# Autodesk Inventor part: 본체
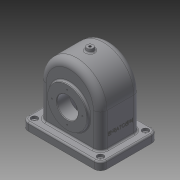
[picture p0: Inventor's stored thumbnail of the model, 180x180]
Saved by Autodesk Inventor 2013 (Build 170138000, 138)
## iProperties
Created: 2016-10
Part Number: 본체
Material: Generic
Document SubType Name: Modeling
Designer: Administrator
Density: 1 g/cm^3
Author: Administrator
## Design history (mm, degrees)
sketch "스케치1"
  geometry: L1 (-58, 65)-(58, 65); L2 (58, 65)-(58, 0); L3 (58, 0)-(-58, 0); L4 (-58, 0)-(-58, 65); L5 (-58, 65)-(-58, 80); L6 (58, 65)-(58, 80); A1 r 58 centre (0, 80) between (58, 80) and (-58, 80); 2 further points
  constraints: 12 end point, 3 parallel, 2 point on circle, 1 centre point, 1 coincident, 1 collinear, 1 horizontal, 1 midpoint, 1 perpendicular, 1 vertical alignment
  dimensions: "d0" = 116 distance of L2.end L3.end; "d2" = 65 distance of L1.end L2.end; "d4" = 80 distance of point (0, 0) A1.centre; "d5" = 58 radius of A1
extrude "돌출1" new body sketch "스케치1" stored distance "d6" = 77; taper "d7" = 0 deg
sketch "스케치2"
  geometry: L1 (58, 80)-(58, 0) reference; L2 (58, 0)-(-58, 0) reference; L3 (-58, 0)-(-58, 80) reference; L4 (52, 80)-(52, -10); L5 (-52, -10)-(-52, 80); L6 (-52, -10)-(52, -10); A1 r 58 centre (0, 80) between (58, 80) and (-58, 80) reference; A2 r 52 centre (0, 80) between (52, 80) and (-52, 80); 1 further point
  constraints: 6 end point, 2 point on circle, 1 centre point, 1 parallel, 1 perpendicular, 1 other
  dimensions: "d8" = 6 distance between parallel lines of L3 L5; "d9" = 52 radius of A2; "d10" = 10 distance between parallel lines of L6 L2
extrude "돌출2" cut sketch "스케치2" stored distance "d11" = 67; taper "d12" = 0 deg
fillet "모깎기1" dims "d13" = 8
fillet "모깎기2" dims "d14" = 13
sketch "스케치5"
  geometry: L1 (132, -25.5)-(132, 25.5) reference; L2 (124, 33.5)-(0, 33.5) reference; L3 (0, 33.5)-(0, 38.5) reference; L4 (0, 38.5)-(125, 38.5) reference; L5 (138, 25.5)-(138, -25.5) reference; L6 (125, -38.5)-(0, -38.5) reference; L7 (0, -38.5)-(0, -33.5) reference; L8 (0, -33.5)-(124, -33.5) reference; L9 (104.747, 33.5)-(93, 19.5); L10 (93, 19.5)-(65, 19.5); L11 (65, 43.5)-(102.5, 43.5); L12 (102.5, 43.5)-(102.5, 38.5); L13 (65, 19.5)-(65, 33.5); L14 (65, 38.5)-(65, 43.5); A1 r 8 centre (124, -25.5) between (124, -33.5) and (132, -25.5) reference; A2 r 8 centre (124, 25.5) between (132, 25.5) and (124, 33.5) reference; A3 r 13 centre (125, 25.5) between (138, 25.5) and (125, 38.5) reference; A4 r 13 centre (125, -25.5) between (125, -38.5) and (138, -25.5) reference; 1 further point
  constraints: 12 end point, 5 perpendicular, 4 point on line, 1 collinear, 1 parallel
  dimensions: "d15" = 65 distance from line of point (0, 0) L13; "d16" = 5 distance of L11.end L12.end; "d18" = 50 deg angle of L10 L9; "d19" = 56 diameter of L9.end L13; "d20" = 75 diameter of L12 L14; "d21" = 14 distance between parallel lines of L2 L10
revolve "회전1" sketch "스케치5" stored, may be unused: angle "d22" = 90 deg
sketch "스케치6"
  geometry: L1 (132, -25.5)-(132, 25.5) reference; L2 (124, 33.5)-(104.747, 33.5) reference; L3 (104.747, 33.5)-(93, 19.5) reference; L4 (93, 19.5)-(37, 19.5) reference; L5 (37, 19.5)-(25.253, 33.5) reference; L6 (25.253, 33.5)-(0, 33.5) reference; L7 (0, 33.5)-(0, 38.5) reference; L8 (0, 38.5)-(27.5, 38.5) reference; L9 (27.5, 38.5)-(27.5, 43.5) reference; L10 (27.5, 43.5)-(102.5, 43.5) reference; L11 (102.5, 43.5)-(102.5, 38.5) reference; L12 (102.5, 38.5)-(125, 38.5) reference; L13 (138, 25.5)-(138, -25.5) reference; L14 (125, -38.5)-(0, -38.5) reference; L15 (0, -38.5)-(0, -33.5) reference; L16 (0, -33.5)-(124, -33.5) reference; L17 (96, -38.5)-(65, -38.5); L18 (65, -38.5)-(65, -48.5); L19 (65, -48.5)-(96, -48.5); L20 (96, -48.5)-(96, -38.5); A1 r 8 centre (124, -25.5) between (124, -33.5) and (132, -25.5) reference; A2 r 8 centre (124, 25.5) between (132, 25.5) and (124, 33.5) reference; A3 r 13 centre (125, 25.5) between (138, 25.5) and (125, 38.5) reference; A4 r 13 centre (125, -25.5) between (125, -38.5) and (138, -25.5) reference; 1 further point
  constraints: 8 end point, 2 parallel, 1 horizontal, 1 perpendicular, 1 point on line
  dimensions: "d23" = 10 distance of L19.end L17.start; "d25" = 65 distance from line of point (0, 0) L18; "d26" = 62 diameter of L20 L18
revolve "회전2" sketch "스케치6" stored, may be unused: angle "d27" = 90 deg
hole "구멍1" diameter "d30" = 40; stored, may be unused: countersink angle "d34" = 90 deg, drill point angle "d36" = 118 deg; dims "d31" = 6, "d32" = 4, "d33" = 2, "d35" = 127.5, "d37" = 10, "d38" = 10
sketch "스케치7"
  geometry: L1 (103, -64)-(103, -13) reference; L2 (0, 0)-(90, 0) reference; L3 (-13, -64)-(-13, -13) reference; L4 (90, -77)-(0, -77) reference; L5 (-30, -93.5)-(120, -93.5); L6 (120, -93.5)-(120, 16.5); L7 (120, 16.5)-(-30, 16.5); L8 (-30, 16.5)-(-30, -93.5); L9 (-30, -93.5)-(120, 16.5); L10 (120, -93.5)-(-30, 16.5); A1 r 13 centre (90, -64) between (90, -77) and (103, -64) reference; A2 r 13 centre (90, -13) between (103, -13) and (90, 0) reference; A3 r 13 centre (0, -13) between (0, 0) and (-13, -13) reference; A4 r 13 centre (0, -64) between (-13, -64) and (0, -77) reference; 1 further point
  constraints: 12 end point, 2 midpoint, 2 parallel, 1 horizontal, 1 perpendicular
  dimensions: "d39" = 110 distance of L5.end L6.end; "d41" = 150 distance of L5.start L5.end
extrude "돌출3" join sketch "스케치7" distance "d42" = 15; taper "d43" = 0 deg
fillet "모깎기3" dims "d44" = 12
hole "구멍2" diameter "d47" = 5; stored, may be unused: countersink angle "d51" = 90 deg, drill point angle "d53" = 118 deg; dims "d45" = 10, "d46" = 10, "d48" = 6, "d49" = 12, "d50" = 5, "d52" = 25
sketch "스케치9"
  geometry: L1 (34, -48.5)-(34, -38.5) reference; L2 (34, -38.5)-(15, -38.5) reference; L3 (15, -38.5)-(15, -55) reference; L4 (15, -55)-(0, -55) reference; L5 (0, -55)-(0, -33.5) reference; L6 (0, -33.5)-(45, -33.5) reference; L7 (45, -33.5)-(45, -48.5) reference; L8 (45, -48.5)-(34, -48.5) reference; L9 (37, 19.5)-(25.253, 33.5) reference; L10 (25.253, 33.5)-(0, 33.5) reference; L11 (0, 33.5)-(0, 55) reference; L12 (0, 55)-(15, 55) reference; L13 (15, 55)-(15, 38.5) reference; L14 (15, 38.5)-(27.5, 38.5) reference; L15 (27.5, 38.5)-(27.5, 43.5) reference; L16 (27.5, 43.5)-(45, 43.5) reference; L17 (45, 43.5)-(45, 19.5) reference; L18 (45, 19.5)-(37, 19.5) reference; L19 (132, -25.5)-(132, 25.5) reference; L20 (124, 33.5)-(104.747, 33.5) reference; L21 (104.747, 33.5)-(93, 19.5) reference; L22 (93, 19.5)-(85, 19.5) reference; L23 (85, 19.5)-(85, 43.5) reference; L24 (85, 43.5)-(102.5, 43.5) reference; L25 (102.5, 43.5)-(102.5, 38.5) reference; L26 (102.5, 38.5)-(125, 38.5) reference; L27 (138, 25.5)-(138, -25.5) reference; L28 (125, -38.5)-(96, -38.5) reference; L29 (96, -38.5)-(96, -48.5) reference; L30 (96, -48.5)-(85, -48.5) reference; L31 (85, -48.5)-(85, -33.5) reference; L32 (85, -33.5)-(124, -33.5) reference; L33 (136, 0)-(144, 0); L34 (144, 0)-(144, -6); L35 (144, -6)-(136, -7.411); L36 (136, -7.411)-(136, 0); L37 (0, 0)-(169.464, 0); A1 r 8 centre (124, -25.5) between (124, -33.5) and (132, -25.5) reference; A2 r 8 centre (124, 25.5) between (132, 25.5) and (124, 33.5) reference; A3 r 13 centre (125, 25.5) between (138, 25.5) and (125, 38.5) reference; A4 r 13 centre (125, -25.5) between (125, -38.5) and (138, -25.5) reference
  constraints: 10 end point, 2 parallel, 2 perpendicular, 1 collinear
  dimensions: "d65" = 100 deg angle of L35 L27; "d66" = 144 distance from line of L37.start L34; "d68" = 6 distance of L33.end L34.end; "d71" = 2 distance between parallel lines of L36 L27
revolve "회전3" sketch "스케치9" stored, may be unused: angle "d72" = 90 deg
hole "구멍3" diameter "d76" = 4.459; stored, may be unused: countersink angle "d80" = 90 deg, drill point angle "d82" = 118 deg; dims "d74" = 10, "d75" = 10, "d77" = 15, "d78" = 12, "d79" = 5, "d81" = 20
sketch "스케치12"
  geometry: C1 r 20 at (0, 0) reference; 2 further points
  constraints: 1 vertical alignment
  dimensions: "d83" = 29 distance of C1.centre point (0, 29)
hole "구멍4" sketch "스케치12" at (0, 29) diameter "d84" = 2.459; stored, may be unused: countersink angle "d88" = 90 deg, drill point angle "d90" = 118 deg; dims "d85" = 6, "d86" = 12, "d87" = 5, "d89" = 8
sketch "스케치13"
  geometry: C1 r 20 at (0, 0) reference; 2 further points
  constraints: 1 vertical alignment
  dimensions: "d94" = 26 distance of C1.centre point (0, 26)
hole "구멍5" sketch "스케치13" at (0, 26) diameter "d95" = 2.459; stored, may be unused: countersink angle "d99" = 90 deg, drill point angle "d101" = 118 deg; dims "d96" = 6, "d97" = 12, "d98" = 5, "d100" = 8
sketch "스케치14" dims "d0" = 116, "d2" = 65, "d4" = 80, "d5" = 58
  geometry: L1 (86, 0)-(0, 0) reference; L2 (4.5, 80)-(4.5, 15) reference; 2 further points
  constraints: 1 other
  dimensions: "d105" = 38.5 distance from line of L2 point (43, 40); "d106" = 40 distance from line of L1 point (43, 40)
feature "엠보싱1" sketch "스케치14" dims "d0" = 116, "d2" = 65, "d4" = 80, "d5" = 58, "d107" = 0.5, "d108" = 0
fillet "모깎기4" dims "d109" = 3
fillet "모깎기5" dims "d110" = 3
fillet "모깎기6" dims "d111" = 3
fillet "모깎기7" dims "d112" = 3
chamfer "모따기1" distance "d113" = 1; stored, may be unused: second distance "d114" = 2, angle "d115" = 45 deg
node "솔리드1"
pattern_linear "직사각형 패턴1" dims "d56" = 126, "d59" = 86
pattern_circular "원형 패턴1" dims angle "d92" = 360 deg
pattern_circular "원형 패턴2" dims angle "d103" = 360 deg
node "절단 모서리 투영1"
node "절단 모서리 투영4"
node "절단 모서리 투영5"
node "절단 모서리 투영6"
